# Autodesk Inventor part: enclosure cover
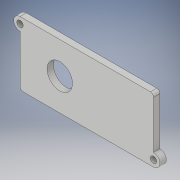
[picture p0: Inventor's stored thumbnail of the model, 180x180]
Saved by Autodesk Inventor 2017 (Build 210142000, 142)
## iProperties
Created: 2016-08
Part Number: enclosure cover
Material: Generic
Document SubType Name: Modeling
Designer: Stan
Density: 1 g/cm^3
Appearance: Default
Author: Stan
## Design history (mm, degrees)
sketch "Sketch1"
  geometry: L1 (33.767, 14.301)-(-32.908, 14.301); L2 (-32.908, 7.951)-(-32.908, -17.449); L3 (-32.908, -17.449)-(33.767, -17.449); L4 (33.767, -11.099)-(33.767, 14.301); C1 r 1.587 at (33.767, -14.274); C2 r 1.588 at (-32.908, 11.126); A1 r 3.175 centre (-32.908, 11.126) between (-32.908, 14.301) and (-32.908, 7.951); A2 r 3.175 centre (33.767, -14.274) between (33.767, -17.449) and (33.767, -11.099); 1 further point
  constraints: 8 end point, 4 centre point, 4 point on circle
extrude "Extrusion1" new body sketch "Sketch1" distance "d0" = 3.175; taper "d1" = 0 deg
fillet "Fillet1" dims "d2" = 1.5875
sketch "Sketch2"
  geometry: L1 (-32.908, 7.951)-(-32.908, -15.861) reference; L2 (32.179, 14.301)-(-32.908, 14.301) reference; C1 r 6.35 at (-13.071, -1.582); 1 further point
  constraints: 1 centre point
  dimensions: "d3" = 19.8374 distance from line of C1.centre L1; "d4" = 15.88364 distance from line of C1.centre L2; "d5" = 12.7 diameter of C1
extrude "Extrusion2" cut sketch "Sketch2" distance "d6" = 3.175; taper "d7" = 0 deg
body "Solid1"
